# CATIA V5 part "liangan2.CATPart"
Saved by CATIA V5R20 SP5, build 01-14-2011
Part number: 连杆2
Bounding box of the stored display mesh (mm): x -20 to 170, y -20 to 20, z 0 to 40
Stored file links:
  E:\scc\liangan\liangan2.CATPart
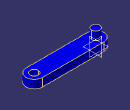
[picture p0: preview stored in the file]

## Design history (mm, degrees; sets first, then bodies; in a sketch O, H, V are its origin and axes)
Body1 (main body)
  Sketch1 on xy-plane, origin (0, 0, 0), H (1, 0, 0), V (0, 1, 0)
    construction line L1 (0, 0) -> (150, 0)
    line L2 (0, 20) -> (150, 20)
    line L3 (150, -20) -> (0, -20)
    arc A1 centre (150, 0) radius 20 from (150, 20) to (150, -20) cw
    arc A2 centre (0, 0) radius 20 from (0, -20) to (0, 20) cw
    circle A3 centre (150, 0) radius 10
    distance L1 L2 = 20
    radius A3 = 10
    horizontal: L1 H
    tangency: A1 L2, A2 L2, A1 L3, A2 L3
  Pad1: profile Sketch1, direction (0, 0, 1), length 20
  Sketch2 on end face of Pad1, origin (0, 0, 20), H (1, 0, 0), V (0, 1, 0)
    circle A1 centre (0, 0) radius 10
    radius A1 = 10
  Pad2: profile Sketch2, direction (0, 0, 1), length 20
